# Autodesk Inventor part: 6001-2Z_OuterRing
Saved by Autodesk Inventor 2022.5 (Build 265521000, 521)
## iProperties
Created: 2024-12
Part Number: 6001-2Z_OuterRing
Material: Generic
Document SubType Name: Modeling
Designer: AdminForWorker
Density: 1 g/cm^3
Appearance: Default
Title: 6001-2Z_OuterRing
Author: AdminForWorker
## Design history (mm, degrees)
feature "Body1"
body "Solid1"
